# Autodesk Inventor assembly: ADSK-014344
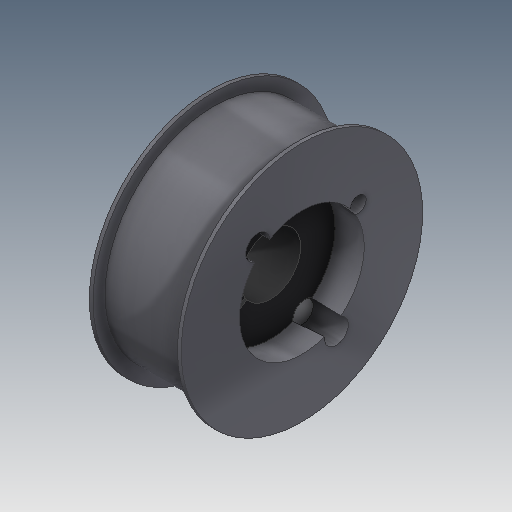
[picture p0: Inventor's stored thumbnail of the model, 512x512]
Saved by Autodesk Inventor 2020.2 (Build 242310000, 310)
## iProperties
Created: 2019-10
Part Number: ADSK-014344
Document SubType Name: Assembly
Designer: lutzd
Mass: 1594.53 g
Surface Area: 456.675 cm^2
Volume: 202.816 cm^3
Density: 7.86192 g/cm^3
VLDS_Profile: Default Assembly
VLDS_TimeStamp: 2016-07-29
VLDS_FailCnt: 0
VLDS_AcceptCnt: 0
Dimensions: 100x100x38 mm
Mass: 1,595 kg
DocNumber: ADSK-014344
Folder: 01 - Themengebiete\Simplification\01 - Packaging machine\
VDS_Category: 3D Komponenten
VDS_NumSchm: Autodesk
Title: wheel
Author: lutzd
Revision Number: -
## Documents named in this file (5)
- D:\07 - DEMODATEN\OTX 2019 - Dataset - UPDATE - Dez2019\Designs\07-Packing machine\ADSK-014344.iam
- D:\07 - DEMODATEN\OTX 2019 - Dataset - UPDATE - Dez2019\Designs\07-Packing machine\Parts\ADSK-011718.ipt
- D:\07 - DEMODATEN\OTX 2019 - Dataset - UPDATE - Dez2019\Designs\07-Packing machine\Parts\ADSK-011820.ipt
- D:\07 - DEMODATEN\OTX 2019 - Dataset - UPDATE - Dez2019\Content Center Files\de-DE\ISO 2338(2)\ISO 2338 - 10 m6 x 24.ipt
- D:\07 - DEMODATEN\OTX 2019 - Dataset - UPDATE - Dez2019\Content Center Files\de-DE\ISO 4026\ISO 4026 - M8 x 25 - ISO.ipt
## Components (5 placed, 4 different names)
1. ADSK-011718:1 — Passend:2, Einfügen:2
2. ADSK-011820:1 — Passend:2, Einfügen:1
3. ISO 2338 10 m6 x 24:1 — Einfügen:2
4. ISO 2338 10 m6 x 24:2 — Einfügen:1
5. ISO 4026 M8 x 25:1
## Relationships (3: Insert 2, Mate 1)
- Passend:2 [Mate]: ADSK-011718:1 ↔ ADSK-011820:1
- Einfügen:1 [Insert]: ADSK-011820:1 ↔ ISO 2338 10 m6 x 24:2
- Einfügen:2 [Insert]: ADSK-011718:1 ↔ ISO 2338 10 m6 x 24:1
